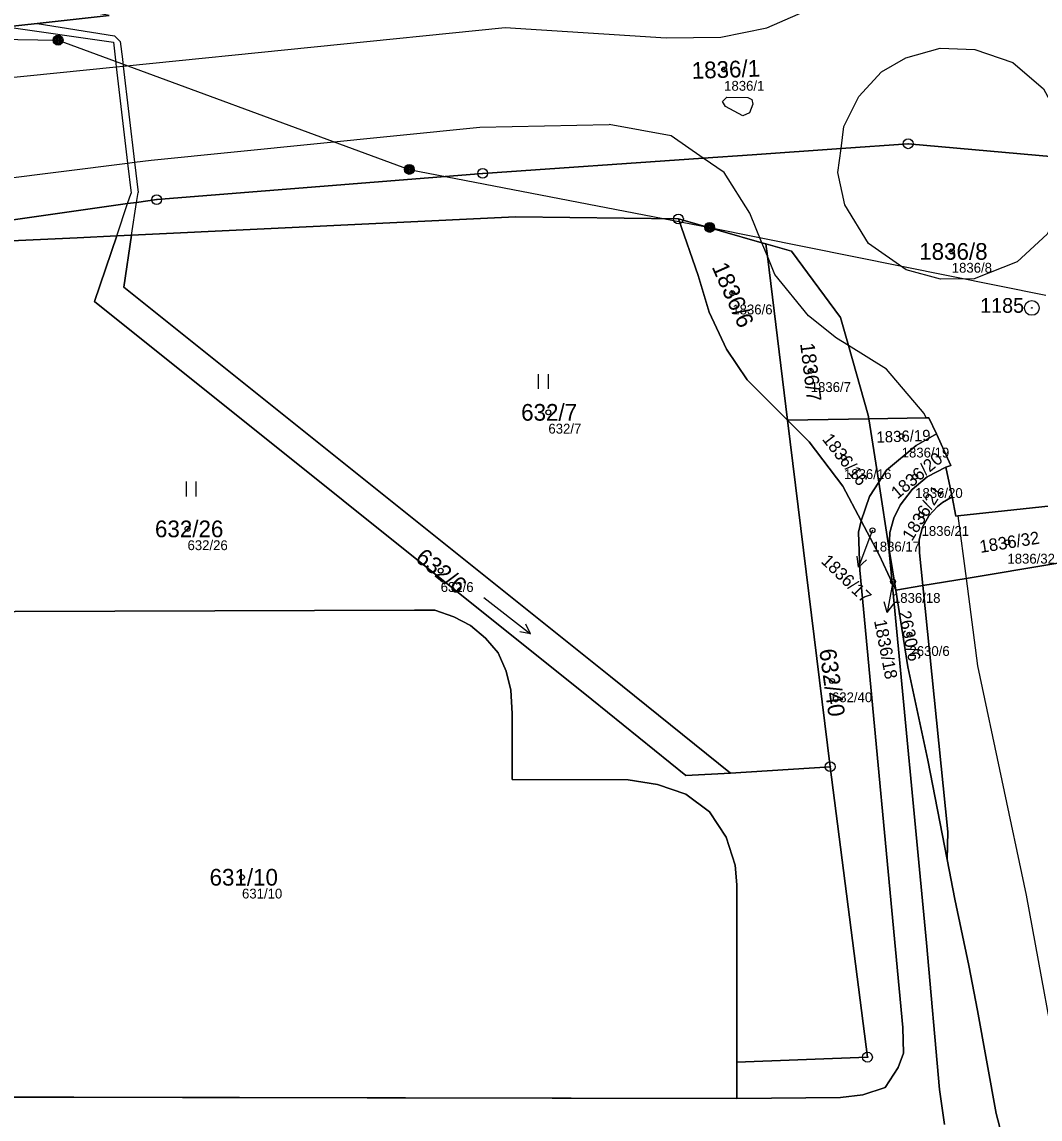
# Model space of a CAD drawing. Extents: x -653098 to -649479, y -997642 to -992666.
# Drawn here: x -652333.4 to -652229.9, y -995042.1 to -994930.5 of the extents above; entities that cross this region are included whole.
import ezdxf

# ---------------------------------------------------------------- set-up
doc = ezdxf.new("R2010")
doc.units = 0
for name, color, linetype in [('Definiční body', 7, 'Continuous'), ('Hranice parcel', 7, 'Continuous'), ('Parcelní čísla', 7, 'Continuous'), ('Polygon parcely', 7, 'Continuous'), ('Pop  PČ popisy', 7, 'Continuous'), ('Poz předměty', 7, 'Continuous'), ('Vnitřní kresba', 7, 'Continuous'), ('Značky bodu BP', 7, 'Continuous'), ('Značky kultur', 7, 'Continuous')]:
    doc.layers.add(name, color=color, linetype=linetype)

msp = doc.modelspace()

# ---------------------------------------------------------------- linework, layer by layer
at = {"layer": 'Definiční body'}
for centre in [(-652262.01, -994935.34), (-652238.87, -994953.84), (-652261.18, -994958.08), (-652253.21, -994965.97), (-652279.88, -994970.2), (-652243.96, -994972.63), (-652249.83, -994974.82), (-652242.59, -994976.74), (-652241.94, -994980.6), (-652316.57, -994982.05), (-652246.93, -994982.19), (-652233.21, -994983.42), (-652290.83, -994986.3), (-652244.85, -994987.41), (-652243.17, -994992.81), (-652251.05, -994997.51), (-652311.03, -995017.47)]:
    msp.add_circle(centre, 0.25, dxfattribs=at)
at = {"layer": 'Hranice parcel'}
for p, q in [((-652322.26, -994952.18), (-652323.77, -994952.25)), ((-652255.57, -994970.99), (-652247.31, -994970.85)), ((-652251.23, -995006.23), (-652255.57, -994970.99)), ((-652246.3, -994977.31), (-652247.31, -994970.85)), ((-652239.47, -994975.77), (-652238.83, -994978.8)), ((-652245.22, -994984.15), (-652246.3, -994977.31)), ((-652244.57, -994988.28), (-652245.22, -994984.15)), ((-652244.57, -994988.28), (-652244.92, -994987.54)), ((-652244.57, -994988.28), (-652241.8, -994987.82)), ((-652261.37, -995006.9), (-652251.23, -995006.23)), ((-652260.73, -995039.97), (-652260.73, -995036.27)), ((-652345.02, -995039.8), (-652260.73, -995039.97))]:
    msp.add_line(p, q, dxfattribs=at)
for points in [[(-652324.54, -994929.86), (-652331.85, -994930.65), (-652334.96, -994930.99)], [(-652344.95, -994953.25), (-652365.71, -994954.24), (-652336.24, -994950.88), (-652322.66, -994948.98), (-652321.75, -994948.86), (-652319.7, -994948.57), (-652286.56, -994945.9), (-652264.13, -994944.34), (-652259.17, -994944), (-652250.13, -994943.37), (-652243.3, -994942.89), (-652226.94, -994944.36), (-652217.56, -994945.2), (-652208.03, -994946.05)], [(-652266.66, -994950.54), (-652283.22, -994950.32), (-652322.26, -994952.18)], [(-652255.57, -994970.99), (-652259.68, -994966.91), (-652261.77, -994963.76), (-652263.52, -994960), (-652264.65, -994956.28), (-652266.66, -994950.54)], [(-652257.77, -994953.07), (-652258.18, -994952.95), (-652266.66, -994950.54)], [(-652323.77, -994952.25), (-652327.8, -994952.44), (-652344.95, -994953.25)], [(-652323.77, -994952.25), (-652326.04, -994958.94), (-652275.46, -994999.39), (-652265.89, -995007.11), (-652261.37, -995006.9)], [(-652261.37, -995006.9), (-652273.58, -994997.05), (-652323.06, -994957.48), (-652322.26, -994952.18)], [(-652255.57, -994970.99), (-652257.62, -994954.33), (-652257.77, -994953.07)], [(-652247.31, -994970.85), (-652247.37, -994970.49), (-652249.36, -994963.41), (-652250.17, -994960.55), (-652255.15, -994953.81), (-652257.77, -994953.07)], [(-652260.73, -995036.27), (-652260.73, -995018.23), (-652260.88, -995016.23), (-652261.82, -995013.38), (-652263.5, -995010.83), (-652265.91, -995009.01), (-652268.79, -995008.03), (-652271.78, -995007.58), (-652283.57, -995007.53), (-652283.57, -995000.83), (-652283.7, -994998.45), (-652284.18, -994996.5), (-652285, -994994.66), (-652286.26, -994993.16), (-652287.79, -994991.88), (-652289.51, -994991), (-652291.42, -994990.32), (-652293.48, -994990.32), (-652344.29, -994990.49), (-652348.89, -994989.71), (-652353.2, -994977.37), (-652354.89, -994963.45), (-652354, -994958.11), (-652352.11, -994954.23)], [(-652248.08, -994981.23), (-652249.94, -994977.69), (-652253.35, -994973.19), (-652255.57, -994970.99)], [(-652247.31, -994970.85), (-652241.46, -994970.76), (-652241.21, -994970.76), (-652240.43, -994972.4)], [(-652246.3, -994977.31), (-652245.51, -994976.08), (-652242.49, -994973.58), (-652240.43, -994972.4)], [(-652240.43, -994972.4), (-652238.96, -994975.61), (-652239.47, -994975.77)], [(-652245.22, -994984.15), (-652245.16, -994982.41), (-652244.76, -994980.97), (-652244.11, -994979.64), (-652242.9, -994978.05), (-652241.37, -994976.77), (-652239.47, -994975.77)], [(-652248.08, -994981.23), (-652247.23, -994978.77), (-652246.3, -994977.31)], [(-652241.8, -994987.82), (-652242.14, -994984.5), (-652242.17, -994983.15), (-652241.85, -994981.87), (-652241.21, -994980.72), (-652240.33, -994979.78), (-652239.8, -994979.36), (-652238.83, -994978.8)], [(-652238.83, -994978.8), (-652238.46, -994980.75), (-652238.25, -994980.73), (-652228.75, -994979.69)], [(-652248.08, -994981.23), (-652248.35, -994982.39), (-652248.22, -994986.25), (-652243.83, -995032.74), (-652243.79, -995035.34), (-652244.33, -995036.82), (-652245.65, -995038.86), (-652247.9, -995039.59), (-652250.17, -995039.85), (-652260.73, -995039.97)], [(-652244.92, -994987.54), (-652246.26, -994984.69), (-652248.08, -994981.23)], [(-652244.92, -994987.54), (-652245.23, -994984.39), (-652245.22, -994984.15)], [(-652241.8, -994987.82), (-652237.42, -994987.09), (-652228.28, -994985.56), (-652220.31, -994984.24)], [(-652244.92, -994987.54), (-652241.44, -995024.14), (-652240.13, -995039.05), (-652239.62, -995042.62)], [(-652239.33, -995015.66), (-652241.29, -995005.58), (-652243.35, -994996.07), (-652244.57, -994988.28)], [(-652241.8, -994987.82), (-652239.28, -995012.86), (-652239.33, -995015.66)], [(-652260.73, -995036.27), (-652247.44, -995035.76), (-652251.23, -995006.23)], [(-652201.45, -995145.65), (-652203.6, -995140.1), (-652217.5, -995099.76), (-652226.42, -995071.77), (-652234.34, -995041.48), (-652236.25, -995031.01), (-652237.13, -995026.45), (-652238.55, -995019.7), (-652239.33, -995015.66)]]:
    msp.add_lwpolyline(points, dxfattribs=at)
at = {"layer": 'Polygon parcely'}
for points in [[(-652373.02, -994923.85), (-652350.23, -994928.4), (-652334.96, -994930.99), (-652331.85, -994930.65), (-652324.54, -994929.86), (-652349.46, -994925.03), (-652371.56, -994920.73), (-652401.34, -994907.86), (-652437.04, -994890.91), (-652459.5, -994880.11), (-652457.89, -994883.93), (-652438.33, -994893.12), (-652403, -994909.87)], [(-652266.66, -994950.54), (-652283.22, -994950.32), (-652322.26, -994952.18), (-652323.06, -994957.48), (-652273.58, -994997.05), (-652261.37, -995006.9), (-652251.23, -995006.23), (-652255.57, -994970.99), (-652259.68, -994966.91), (-652261.77, -994963.76), (-652263.52, -994960), (-652264.65, -994956.28)], [(-652257.62, -994954.33), (-652257.77, -994953.07), (-652258.18, -994952.95), (-652266.66, -994950.54), (-652264.65, -994956.28), (-652263.52, -994960), (-652261.77, -994963.76), (-652259.68, -994966.91), (-652255.57, -994970.99)], [(-652265.89, -995007.11), (-652261.37, -995006.9), (-652273.58, -994997.05), (-652323.06, -994957.48), (-652322.26, -994952.18), (-652323.77, -994952.25), (-652326.04, -994958.94), (-652275.46, -994999.39)], [(-652250.17, -994960.55), (-652255.15, -994953.81), (-652257.77, -994953.07), (-652257.62, -994954.33), (-652255.57, -994970.99), (-652247.31, -994970.85), (-652247.37, -994970.49), (-652249.36, -994963.41)], [(-652248.08, -994981.23), (-652249.94, -994977.69), (-652253.35, -994973.19), (-652255.57, -994970.99), (-652251.23, -995006.23), (-652247.44, -995035.76), (-652260.73, -995036.27), (-652260.73, -995039.97), (-652250.17, -995039.85), (-652247.9, -995039.59), (-652245.65, -995038.86), (-652244.33, -995036.82), (-652243.79, -995035.34), (-652243.83, -995032.74), (-652248.22, -994986.25), (-652248.35, -994982.39)], [(-652247.31, -994970.85), (-652255.57, -994970.99), (-652253.35, -994973.19), (-652249.94, -994977.69), (-652248.08, -994981.23), (-652247.23, -994978.77), (-652246.3, -994977.31)], [(-652246.3, -994977.31), (-652245.51, -994976.08), (-652242.49, -994973.58), (-652240.43, -994972.4), (-652241.21, -994970.76), (-652241.46, -994970.76), (-652247.31, -994970.85)], [(-652239.47, -994975.77), (-652238.96, -994975.61), (-652240.43, -994972.4), (-652242.49, -994973.58), (-652245.51, -994976.08), (-652246.3, -994977.31), (-652245.22, -994984.15), (-652245.16, -994982.41), (-652244.76, -994980.97), (-652244.11, -994979.64), (-652242.9, -994978.05), (-652241.37, -994976.77)], [(-652241.8, -994987.82), (-652242.14, -994984.5), (-652242.17, -994983.15), (-652241.85, -994981.87), (-652241.21, -994980.72), (-652240.33, -994979.78), (-652239.8, -994979.36), (-652238.83, -994978.8), (-652239.47, -994975.77), (-652241.37, -994976.77), (-652242.9, -994978.05), (-652244.11, -994979.64), (-652244.76, -994980.97), (-652245.16, -994982.41), (-652245.22, -994984.15), (-652244.57, -994988.28)], [(-652246.3, -994977.31), (-652247.23, -994978.77), (-652248.08, -994981.23), (-652246.26, -994984.69), (-652244.92, -994987.54), (-652245.23, -994984.39), (-652245.22, -994984.15)], [(-652237.42, -994987.09), (-652228.28, -994985.56), (-652220.31, -994984.24), (-652221.2, -994978.97), (-652228.29, -994979.65), (-652228.75, -994979.69), (-652238.25, -994980.73), (-652238.46, -994980.75), (-652238.83, -994978.8), (-652239.8, -994979.36), (-652240.33, -994979.78), (-652241.21, -994980.72), (-652241.85, -994981.87), (-652242.17, -994983.15), (-652242.14, -994984.5), (-652241.8, -994987.82)], [(-652245.22, -994984.15), (-652245.23, -994984.39), (-652244.92, -994987.54), (-652244.57, -994988.28)], [(-652239.28, -995012.86), (-652239.33, -995015.66), (-652238.55, -995019.7), (-652237.13, -995026.45), (-652236.25, -995031.01), (-652234.34, -995041.48), (-652226.42, -995071.77), (-652217.5, -995099.76), (-652203.6, -995140.1), (-652201.45, -995145.65), (-652202.44, -995124.3), (-652204.26, -995085.16), (-652205.81, -995051.7), (-652206.12, -995050.59), (-652209.21, -995036.23), (-652212.94, -995018.29), (-652216.1, -995003.91), (-652218.88, -994992.43), (-652220.31, -994984.24), (-652228.28, -994985.56), (-652237.42, -994987.09), (-652241.8, -994987.82)], [(-652239.33, -995015.66), (-652239.28, -995012.86), (-652241.8, -994987.82), (-652244.57, -994988.28), (-652243.35, -994996.07), (-652241.29, -995005.58)]]:
    msp.add_lwpolyline(points, close=True, dxfattribs=at)
for points in [[(-652324.54, -994929.86), (-652331.85, -994930.65), (-652334.96, -994930.99)], [(-652477.74, -994968.11), (-652408.08, -994959.08), (-652399.46, -994958.98), (-652377.67, -994956.86), (-652352.11, -994954.23), (-652344.95, -994953.25), (-652365.71, -994954.24), (-652336.24, -994950.88), (-652322.66, -994948.98), (-652321.75, -994948.86), (-652319.7, -994948.57), (-652286.56, -994945.9), (-652264.13, -994944.34), (-652259.17, -994944), (-652250.13, -994943.37), (-652243.3, -994942.89), (-652226.94, -994944.36), (-652217.56, -994945.2), (-652208.03, -994946.05), (-652205.95, -994946.24), (-652191.1, -994947.58), (-652175.22, -994950.5), (-652159.22, -994955.49), (-652142.25, -994960.79)], [(-652226.94, -994944.36), (-652243.3, -994942.89), (-652250.13, -994943.37), (-652259.17, -994944), (-652264.13, -994944.34), (-652286.56, -994945.9), (-652319.7, -994948.57), (-652321.75, -994948.86), (-652322.66, -994948.98), (-652336.24, -994950.88)], [(-652344.95, -994953.25), (-652327.8, -994952.44), (-652323.77, -994952.25), (-652322.26, -994952.18), (-652283.22, -994950.32), (-652266.66, -994950.54), (-652258.18, -994952.95), (-652257.77, -994953.07), (-652255.15, -994953.81), (-652250.17, -994960.55), (-652249.36, -994963.41), (-652247.37, -994970.49), (-652247.31, -994970.85), (-652241.46, -994970.76), (-652241.21, -994970.76), (-652240.43, -994972.4), (-652238.96, -994975.61), (-652239.47, -994975.77), (-652238.83, -994978.8), (-652238.46, -994980.75), (-652238.25, -994980.73), (-652228.75, -994979.69)], [(-652344.29, -994990.49), (-652293.48, -994990.32), (-652291.42, -994990.32), (-652289.51, -994991), (-652287.79, -994991.88), (-652286.26, -994993.16), (-652285, -994994.66), (-652284.18, -994996.5), (-652283.7, -994998.45), (-652283.57, -995000.83), (-652283.57, -995007.53), (-652271.78, -995007.58), (-652268.79, -995008.03), (-652265.91, -995009.01), (-652263.5, -995010.83), (-652261.82, -995013.38), (-652260.88, -995016.23), (-652260.73, -995018.23), (-652260.73, -995036.27), (-652247.44, -995035.76), (-652251.23, -995006.23), (-652261.37, -995006.9), (-652265.89, -995007.11), (-652275.46, -994999.39), (-652326.04, -994958.94), (-652323.77, -994952.25), (-652327.8, -994952.44), (-652344.95, -994953.25)], [(-652239.62, -995042.62), (-652240.13, -995039.05), (-652241.44, -995024.14), (-652244.92, -994987.54), (-652246.26, -994984.69), (-652248.08, -994981.23), (-652248.35, -994982.39), (-652248.22, -994986.25), (-652243.83, -995032.74), (-652243.79, -995035.34), (-652244.33, -995036.82), (-652245.65, -995038.86), (-652247.9, -995039.59), (-652250.17, -995039.85), (-652260.73, -995039.97), (-652345.02, -995039.8), (-652344.92, -995050.22)], [(-652226.42, -995071.77), (-652234.34, -995041.48), (-652236.25, -995031.01), (-652237.13, -995026.45), (-652238.55, -995019.7), (-652239.33, -995015.66), (-652241.29, -995005.58), (-652243.35, -994996.07), (-652244.57, -994988.28), (-652244.92, -994987.54), (-652241.44, -995024.14), (-652240.13, -995039.05), (-652239.62, -995042.62)], [(-652345.02, -995039.8), (-652260.73, -995039.97), (-652260.73, -995036.27), (-652260.73, -995018.23), (-652260.88, -995016.23), (-652261.82, -995013.38), (-652263.5, -995010.83), (-652265.91, -995009.01), (-652268.79, -995008.03), (-652271.78, -995007.58), (-652283.57, -995007.53), (-652283.57, -995000.83), (-652283.7, -994998.45), (-652284.18, -994996.5), (-652285, -994994.66), (-652286.26, -994993.16), (-652287.79, -994991.88), (-652289.51, -994991), (-652291.42, -994990.32), (-652293.48, -994990.32), (-652344.29, -994990.49)]]:
    msp.add_lwpolyline(points, dxfattribs=at)
at = {"layer": 'Pop  PČ popisy'}
for p, q in [((-652246.93, -994982.19), (-652247.29, -994983.13)), ((-652247.29, -994983.13), (-652248.36, -994985.93)), ((-652248.36, -994985.93), (-652248.47, -994984.82)), ((-652248.36, -994985.93), (-652247.54, -994985.18)), ((-652244.88, -994987.61), (-652245.45, -994990.56)), ((-652244.85, -994987.41), (-652244.88, -994987.61)), ((-652245.45, -994990.56), (-652245.75, -994989.48)), ((-652245.45, -994990.56), (-652244.77, -994989.67))]:
    msp.add_line(p, q, dxfattribs=at)
at = {"layer": 'Poz předměty'}
for p, q in [((-652360.76, -994931.88), (-652329.73, -994932.36)), ((-652329.73, -994932.36), (-652294.02, -994945.5)), ((-652294.02, -994945.5), (-652263.48, -994951.4)), ((-652263.48, -994951.4), (-652229.32, -994958.27))]:
    msp.add_line(p, q, dxfattribs=at)
for centre, radius in [((-652329.73, -994932.36), 0.5), ((-652329.73, -994932.36), 0.4), ((-652329.73, -994932.36), 0.3), ((-652329.73, -994932.36), 0.2), ((-652329.73, -994932.36), 0.1), ((-652294.02, -994945.5), 0.5), ((-652294.02, -994945.5), 0.4), ((-652294.02, -994945.5), 0.3), ((-652294.02, -994945.5), 0.2), ((-652294.02, -994945.5), 0.1), ((-652263.48, -994951.4), 0.5), ((-652263.48, -994951.4), 0.4), ((-652263.48, -994951.4), 0.3), ((-652263.48, -994951.4), 0.2), ((-652263.48, -994951.4), 0.1)]:
    msp.add_circle(centre, radius, dxfattribs=at)
at = {"layer": 'Vnitřní kresba'}
for p, q in [((-652334.96, -994930.99), (-652324.11, -994932.56)), ((-652331.85, -994930.65), (-652323.98, -994931.91)), ((-652323.11, -994935), (-652284.28, -994931.07)), ((-652324.11, -994932.56), (-652323.89, -994934.38)), ((-652323.98, -994931.91), (-652323.41, -994932.48)), ((-652323.41, -994932.48), (-652323.19, -994934.3)), ((-652323.89, -994934.38), (-652323.81, -994935.07)), ((-652323.19, -994934.3), (-652323.11, -994935)), ((-652323.81, -994935.07), (-652323.11, -994935)), ((-652323.81, -994935.07), (-652322.66, -994944.86)), ((-652323.11, -994935), (-652321.96, -994944.77)), ((-652320.28, -994944.56), (-652286.85, -994941.2)), ((-652286.85, -994941.2), (-652273.69, -994940.92)), ((-652408.72, -994955.61), (-652322.66, -994944.86)), ((-652322.66, -994944.86), (-652321.96, -994944.77)), ((-652322.66, -994944.86), (-652322.3, -994947.92)), ((-652321.96, -994944.77), (-652320.28, -994944.56)), ((-652321.96, -994944.77), (-652321.6, -994947.84)), ((-652322.66, -994948.98), (-652322.3, -994947.92)), ((-652321.75, -994948.86), (-652321.6, -994947.84)), ((-652323.77, -994952.25), (-652322.66, -994948.98)), ((-652322.26, -994952.18), (-652321.75, -994948.86)), ((-652257.62, -994954.33), (-652258.18, -994952.95)), ((-652238.25, -994980.73), (-652237.42, -994987.09)), ((-652237.42, -994987.09), (-652236.26, -994995.97)), ((-652236.26, -994995.97), (-652231.32, -995019.29)), ((-652231.32, -995019.29), (-652227.41, -995040.52))]:
    msp.add_line(p, q, dxfattribs=at)
for points in [[(-652284.28, -994931.07), (-652267.89, -994932.11), (-652262.35, -994932.06), (-652257.66, -994931.12), (-652252.62, -994928.9), (-652248.61, -994925.62)], [(-652250.13, -994943.37), (-652249.83, -994941.15), (-652248.31, -994938.08), (-652246.01, -994935.59), (-652243.53, -994934.16), (-652240.05, -994933.17), (-652236.54, -994933.29), (-652232.67, -994934.64), (-652229.55, -994937.31), (-652227.36, -994941.29), (-652226.94, -994944.36)], [(-652365.49, -994939.48), (-652344.63, -994937.18), (-652323.81, -994935.07)], [(-652259.44, -994939.76), (-652260.11, -994940.05), (-652261.88, -994939.11), (-652262.17, -994938.58), (-652261.74, -994938.16), (-652259.6, -994938.2), (-652259.19, -994938.4), (-652259.11, -994938.87), (-652259.44, -994939.76)], [(-652264.13, -994944.34), (-652267.4, -994942.07), (-652273.69, -994940.92)], [(-652226.94, -994944.36), (-652226.8, -994945.42), (-652227.23, -994948.35), (-652229.18, -994952.08), (-652232.22, -994954.9), (-652236.58, -994956.64), (-652240.01, -994956.65), (-652243.51, -994955.71), (-652247.32, -994953.02), (-652249.75, -994949.09), (-652250.45, -994945.81), (-652250.13, -994943.37)], [(-652258.18, -994952.95), (-652259.4, -994949.95), (-652262, -994945.82), (-652264.13, -994944.34)], [(-652253.43, -994960.37), (-652256.86, -994956.18), (-652257.62, -994954.33)], [(-652249.36, -994963.41), (-652250.59, -994962.65), (-652253.43, -994960.37)], [(-652241.46, -994970.76), (-652241.66, -994970.3), (-652245.5, -994965.82), (-652249.36, -994963.41)]]:
    msp.add_lwpolyline(points, dxfattribs=at)
at = {"layer": 'Značky bodu BP'}
for centre, radius in [((-652243.3, -994942.89), 0.5), ((-652243.3, -994942.89), 0.0303), ((-652286.56, -994945.9), 0.5), ((-652286.56, -994945.9), 0.0303), ((-652319.7, -994948.57), 0.5), ((-652319.7, -994948.57), 0.0303), ((-652266.66, -994950.54), 0.5), ((-652266.66, -994950.54), 0.0303), ((-652230.73, -994959.58), 0.75), ((-652230.73, -994959.58), 0.03), ((-652251.23, -995006.23), 0.5), ((-652251.23, -995006.23), 0.0303), ((-652247.44, -995035.76), 0.5), ((-652247.44, -995035.76), 0.0303)]:
    msp.add_circle(centre, radius, dxfattribs=at)
at = {"layer": 'Značky kultur'}
for p, q in [((-652280.87, -994967.81), (-652280.87, -994966.31)), ((-652279.87, -994967.81), (-652279.87, -994966.31)), ((-652316.69, -994978.74), (-652316.69, -994977.24)), ((-652315.69, -994978.74), (-652315.69, -994977.24)), ((-652286.44, -994989.03), (-652281.71, -994992.72)), ((-652281.71, -994992.72), (-652282.17, -994991.73)), ((-652281.71, -994992.72), (-652282.79, -994992.52))]:
    msp.add_line(p, q, dxfattribs=at)

# ---------------------------------------------------------------- texts
at = {"layer": 'Definiční body'}
for s, p in [('1836/1', (-652262.01, -994937.5)), ('1836/8', (-652238.87, -994956)), ('1836/6', (-652261.18, -994960.24)), ('1836/7', (-652253.21, -994968.13)), ('632/7', (-652279.88, -994972.36)), ('1836/19', (-652243.96, -994974.79)), ('1836/16', (-652249.83, -994976.98)), ('1836/20', (-652242.59, -994978.9)), ('1836/21', (-652241.94, -994982.76)), ('632/26', (-652316.57, -994984.21)), ('1836/17', (-652246.93, -994984.35)), ('1836/32', (-652233.21, -994985.58)), ('632/6', (-652290.83, -994988.46)), ('1836/18', (-652244.85, -994989.57)), ('2630/6', (-652243.17, -994994.97)), ('632/40', (-652251.05, -994999.67)), ('631/10', (-652311.03, -995019.63))]:
    msp.add_text(s, height=1, dxfattribs=at).set_placement(p)
at = {"layer": 'Parcelní čísla'}
for s, height, rotation, p in [('1836/1', 1.7, 2, (-652265.28, -994936.3)), ('1836/6', 1.7, 294, (-652263.3, -994955.41)), ('1836/7', 1.469, 277, (-652254.29, -994963.22)), ('1836/16', 1.271, 308, (-652252.1, -994972.95)), ('1836/19', 1.139, 2, (-652246.51, -994973.29)), ('1836/20', 1.271, 40, (-652244.38, -994979.07)), ('1836/21', 1.271, 58, (-652242.92, -994983.37)), ('1836/32', 1.271, 9, (-652235.94, -994984.5)), ('632/6', 1.7, 321, (-652293.52, -994985.21)), ('1836/17', 1.271, 316, (-652252.23, -994985.43)), ('2630/6', 1.271, 282, (-652244.31, -994990.52)), ('1836/18', 1.271, 281, (-652246.78, -994991.39)), ('632/40', 1.7, 278, (-652252.35, -994994.35))]:
    msp.add_text(s, height=height, rotation=rotation, dxfattribs=at).set_placement(p)
for s, p in [('1836/8', (-652242.18, -994954.69)), ('632/7', (-652282.65, -994971.05)), ('632/26', (-652319.88, -994982.9)), ('631/10', (-652314.33, -995018.32))]:
    msp.add_text(s, height=1.7, dxfattribs=at).set_placement(p)
at = {"layer": 'Značky bodu BP'}
msp.add_text('1185', height=1.5, dxfattribs=at).set_placement((-652235.98, -994960.08))

doc.saveas('drawing.dxf')
